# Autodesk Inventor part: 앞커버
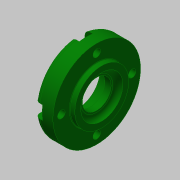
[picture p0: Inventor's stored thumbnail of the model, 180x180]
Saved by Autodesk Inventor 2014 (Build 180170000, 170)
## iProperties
Created: 2015-11
Part Number: 앞커버
Material: 알루미늄 6061
Document SubType Name: Modeling
Designer: mduedu
Density: 1 g/cm^3
Appearance: Dark Green
Author: mduedu
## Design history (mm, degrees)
sketch "스케치1"
  geometry: L1 (-7, 0)-(7, 0); L2 (-7, 0)-(-7, 26); L3 (-7, 26)-(4, 26); L4 (4, 26)-(4, 16); L5 (4, 16)-(7, 16); L6 (7, 16)-(7, 0); 2 further points
  constraints: 12 end point, 3 perpendicular, 2 parallel, 1 coincident, 1 horizontal, 1 midpoint
  dimensions: "d0" = 14 distance of L1.start L1.end; "d1" = 52 diameter of L3 L1; "d2" = 3 distance of L4.end L5.end; "d3" = 32 diameter of L5 L1
revolve "회전1" sketch "스케치1" stored, may be unused: angle "d4" = 90 deg
hole "구멍1" diameter "d7" = 25; stored, may be unused: countersink angle "d11" = 90 deg, drill point angle "d13" = 0 deg; dims "d5" = 10, "d6" = 10, "d8" = 6, "d9" = 4, "d10" = 2, "d12" = 3
hole "구멍2" diameter "d16" = 25; stored, may be unused: countersink angle "d20" = 90 deg, drill point angle "d22" = 0 deg; dims "d17" = 6, "d18" = 4, "d19" = 2, "d21" = 7.3, "d62" = 10, "d63" = 10
hole "구멍3" diameter "d25" = 17; stored, may be unused: countersink angle "d29" = 90 deg, drill point angle "d31" = 0 deg; dims "d23" = 10, "d24" = 10, "d26" = 6, "d27" = 4, "d28" = 2, "d30" = 4.2
chamfer "모따기1" distance "d32" = 0.7; stored, may be unused: second distance "d33" = 2, angle "d34" = 30 deg
fillet "모깎기1" dims "d35" = 0.3
fillet "모깎기2" dims "d36" = 3
fillet "모깎기3" dims "d37" = 3
fillet "모깎기4" dims "d38" = 0.3
sketch "스케치3" dims "d61" = 42
  geometry: C1 r 26 at (0, 0) reference; 2 further points
  constraints: 2 vertical alignment, 1 coincident, 2 other
hole "구멍4" sketch "스케치3" at (0, -21) diameter "d44" = 4.5; stored, may be unused: countersink angle "d48" = 90 deg, drill point angle "d50" = 0 deg; dims "d45" = 6, "d46" = 8, "d47" = 4.6, "d49" = 8
sketch "스케치4"
  geometry: L1 (-4, 0)-(-4, -4.69); L2 (4, 0)-(4, -4.69); A1 r 4 centre (0, 0) between (3.614, -1.714) and (-3.614, -1.714) reference; A2 r 26 centre (0, 21) between (-4, -4.69) and (4, -4.69) reference; 1 further point
  constraints: 4 end point, 4 point on circle, 2 tangent, 1 parallel, 1 vertical
extrude "돌출1" cut sketch "스케치4" stored distance "d51" = 0; taper "d52" = 0 deg
node "솔리드1"
pattern_circular "원형 패턴1" dims angle "d54" = 360 deg
